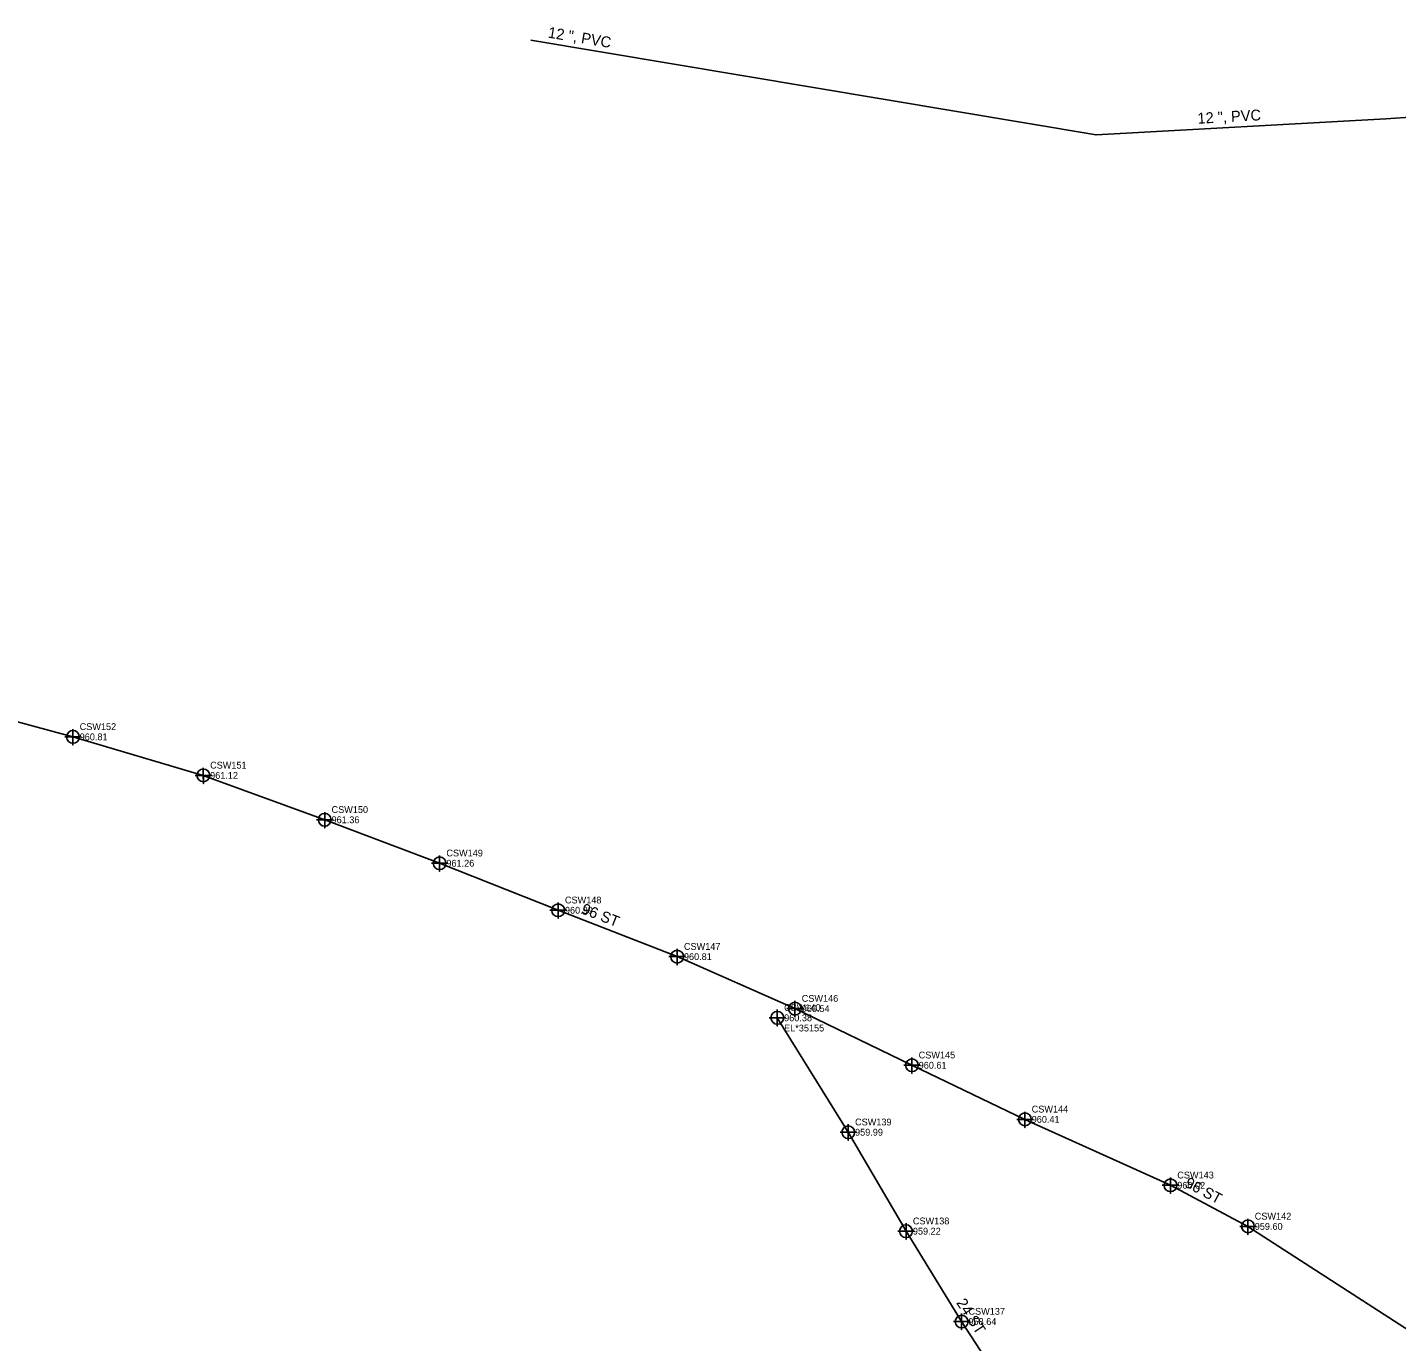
# Model space of a CAD drawing. Extents: x 1182504 to 1186036, y 573002 to 575111.
# Drawn here: x 1183491 to 1183993, y 573983 to 574465 of the extents above; entities that cross this region are included whole.
import ezdxf

# ---------------------------------------------------------------- set-up
doc = ezdxf.new("R2010")
doc.units = 0
for name, color, linetype in [('Exist Utilities Telephone UG Conduit SUE LOS B', 7, 'Continuous'), ('Exist Utilities Telephone UG Conduit SUE LOS B Cogo Elevation', 7, 'Continuous'), ('Exist Utilities Telephone UG Conduit SUE LOS B Cogo Number', 7, 'Continuous'), ('Exist Utilities Telephone UG Conduit SUE LOS B Cogo Point CELL', 7, 'Continuous'), ('Exist Utilities Telephone UG Conduit SUE LOS B Text', 7, 'Continuous'), ('Exist Utilities Telephone UG FO SUE LOS C', 7, 'Continuous'), ('Exist Utilities Telephone UG FO SUE LOS C Cogo Comment', 7, 'Continuous'), ('Exist Utilities Telephone UG FO SUE LOS C Cogo Elevation', 7, 'Continuous'), ('Exist Utilities Telephone UG FO SUE LOS C Cogo Number', 7, 'Continuous'), ('Exist Utilities Telephone UG FO SUE LOS C Cogo Point CELL', 7, 'Continuous'), ('Exist Utilities Telephone UG FO SUE LOS C Text', 7, 'Continuous'), ('Exist Utilities Water UG Line SUE LOS C', 7, 'Continuous'), ('Exist Utilities Water UG Line SUE LOS C Text', 7, 'Continuous')]:
    doc.layers.add(name, color=color, linetype=linetype)

msp = doc.modelspace()

# ---------------------------------------------------------------- linework, layer by layer
at = {"layer": 'Exist Utilities Telephone UG Conduit SUE LOS B'}
msp.add_lwpolyline([(1183461.9, 574217.61), (1183507.97, 574205.1), (1183555.78, 574190.97), (1183600.29, 574174.7), (1183642.38, 574158.78), (1183685.83, 574141.54), (1183729.44, 574124.53), (1183772.61, 574105.48), (1183815.48, 574084.72), (1183856.9, 574064.89), (1183910.26, 574040.72), (1183938.65, 574025.64), (1184017.13, 573974.93), (1184056.25, 573949.51), (1184095.95, 573918.75), (1184120.25, 573896.12), (1184153.18, 573876.37), (1184177.6, 573863.32)], dxfattribs=at)
at = {"layer": 'Exist Utilities Telephone UG Conduit SUE LOS B Cogo Point CELL'}
for points in [[(1183507.95, 574207.92), (1183507.99, 574202.1), (1183507.97, 574205.1), (1183510.99, 574205.1), (1183504.99, 574205.1)], [(1183555.76, 574193.78), (1183555.8, 574187.97), (1183555.78, 574190.97), (1183558.8, 574190.97), (1183552.8, 574190.97)], [(1183600.27, 574177.52), (1183600.3, 574171.7), (1183600.29, 574174.7), (1183603.3, 574174.7), (1183597.3, 574174.7)], [(1183642.36, 574161.59), (1183642.39, 574155.78), (1183642.38, 574158.78), (1183645.39, 574158.78), (1183639.39, 574158.78)], [(1183685.82, 574144.35), (1183685.85, 574138.54), (1183685.83, 574141.54), (1183688.85, 574141.54), (1183682.85, 574141.54)], [(1183729.43, 574127.34), (1183729.46, 574121.53), (1183729.44, 574124.53), (1183732.46, 574124.53), (1183726.46, 574124.53)], [(1183772.6, 574108.3), (1183772.63, 574102.48), (1183772.61, 574105.48), (1183775.63, 574105.48), (1183769.63, 574105.48)], [(1183815.46, 574087.53), (1183815.49, 574081.72), (1183815.48, 574084.72), (1183818.49, 574084.72), (1183812.49, 574084.72)], [(1183856.88, 574067.7), (1183856.91, 574061.89), (1183856.9, 574064.89), (1183859.91, 574064.89), (1183853.91, 574064.89)], [(1183910.25, 574043.54), (1183910.28, 574037.72), (1183910.26, 574040.72), (1183913.28, 574040.72), (1183907.28, 574040.72)], [(1183938.63, 574028.46), (1183938.66, 574022.64), (1183938.65, 574025.64), (1183941.66, 574025.64), (1183935.66, 574025.64)]]:
    msp.add_lwpolyline(points, dxfattribs=at)
for centre in [(1183507.99, 574205.1), (1183555.8, 574190.97), (1183600.3, 574174.7), (1183642.39, 574158.78), (1183685.85, 574141.54), (1183729.46, 574124.53), (1183772.63, 574105.48), (1183815.49, 574084.72), (1183856.91, 574064.89), (1183910.28, 574040.72), (1183938.66, 574025.64)]:
    msp.add_circle(centre, 2.34, dxfattribs=at)
at = {"layer": 'Exist Utilities Telephone UG FO SUE LOS C'}
msp.add_lwpolyline([(1183880.14, 573689.54), (1183880.21, 573736.69), (1183881.09, 573779.07), (1183880.73, 573825.31), (1183881.6, 573871.11), (1183878.51, 573913.09), (1183859.26, 573951.5), (1183833.73, 573990.76), (1183813.35, 574023.89), (1183792.16, 574060.17), (1183766.16, 574102.11)], dxfattribs=at)
at = {"layer": 'Exist Utilities Telephone UG FO SUE LOS C Cogo Point CELL'}
for points in [[(1183766.16, 574105.11), (1183766.16, 574099.11), (1183766.16, 574102.11), (1183769.16, 574102.11), (1183763.16, 574102.11)], [(1183792.16, 574063.17), (1183792.16, 574057.17), (1183792.16, 574060.17), (1183795.16, 574060.17), (1183789.16, 574060.17)], [(1183813.35, 574026.89), (1183813.35, 574020.89), (1183813.35, 574023.89), (1183816.35, 574023.89), (1183810.35, 574023.89)], [(1183833.73, 573993.76), (1183833.73, 573987.76), (1183833.73, 573990.76), (1183836.73, 573990.76), (1183830.73, 573990.76)]]:
    msp.add_lwpolyline(points, dxfattribs=at)
for centre in [(1183766.16, 574102.11), (1183792.16, 574060.17), (1183813.35, 574023.89), (1183833.73, 573990.76)]:
    msp.add_circle(centre, 2.34, dxfattribs=at)
at = {"layer": 'Exist Utilities Water UG Line SUE LOS C'}
msp.add_lwpolyline([(1183675.77, 574460.48), (1183882.99, 574425.76), (1183989.16, 574431.68), (1184300.95, 574453.14)], dxfattribs=at)

# ---------------------------------------------------------------- texts
at = {"layer": 'Exist Utilities Telephone UG Conduit SUE LOS B Cogo Elevation'}
for s, p in [('960.81', (1183510.47, 574203.85)), ('961.12', (1183558.28, 574189.72)), ('961.36', (1183602.79, 574173.45)), ('961.26', (1183644.88, 574157.53)), ('960.99', (1183688.33, 574140.29)), ('960.81', (1183731.94, 574123.28)), ('960.54', (1183775.11, 574104.23)), ('960.61', (1183817.98, 574083.47)), ('960.41', (1183859.4, 574063.64)), ('960.02', (1183912.76, 574039.47)), ('959.60', (1183941.15, 574024.39))]:
    msp.add_text(s, height=2.5, dxfattribs=at).set_placement(p)
at = {"layer": 'Exist Utilities Telephone UG Conduit SUE LOS B Cogo Number'}
for s, p in [('CSW152', (1183510.47, 574207.6)), ('CSW151', (1183558.28, 574193.47)), ('CSW150', (1183602.79, 574177.2)), ('CSW149', (1183644.88, 574161.28)), ('CSW148', (1183688.33, 574144.04)), ('CSW147', (1183731.94, 574127.03)), ('CSW146', (1183775.11, 574107.98)), ('CSW145', (1183817.98, 574087.22)), ('CSW144', (1183859.4, 574067.39)), ('CSW143', (1183912.76, 574043.22)), ('CSW142', (1183941.15, 574028.14))]:
    msp.add_text(s, height=2.5, dxfattribs=at).set_placement(p)
at = {"layer": 'Exist Utilities Telephone UG Conduit SUE LOS B Text'}
for rotation, p in [(338.6924, (1183694.02, 574140.49)), (332.0156, (1183915.17, 574040.38))]:
    msp.add_text('96 ST', height=4, rotation=rotation, dxfattribs=at).set_placement(p)
at = {"layer": 'Exist Utilities Telephone UG FO SUE LOS C Cogo Comment'}
msp.add_text('EL*35155', height=2.5, dxfattribs=at).set_placement((1183768.66, 574097.11))
at = {"layer": 'Exist Utilities Telephone UG FO SUE LOS C Cogo Elevation'}
for s, p in [('960.38', (1183768.66, 574100.86)), ('959.99', (1183794.66, 574058.92)), ('959.22', (1183815.85, 574022.64)), ('958.64', (1183836.23, 573989.51))]:
    msp.add_text(s, height=2.5, dxfattribs=at).set_placement(p)
at = {"layer": 'Exist Utilities Telephone UG FO SUE LOS C Cogo Number'}
for s, p in [('CSW140', (1183768.66, 574104.61)), ('CSW139', (1183794.66, 574062.67)), ('CSW138', (1183815.85, 574026.39)), ('CSW137', (1183836.23, 573993.26))]:
    msp.add_text(s, height=2.5, dxfattribs=at).set_placement(p)
at = {"layer": 'Exist Utilities Telephone UG FO SUE LOS C Text'}
msp.add_text('24 ST', height=4, rotation=303.037, dxfattribs=at).set_placement((1183831.63, 573997.65))
at = {"layer": 'Exist Utilities Water UG Line SUE LOS C Text'}
for rotation, p in [(350.4892, (1183681.92, 574461.47)), (3.1913, (1183920.27, 574429.84))]:
    msp.add_text('12 ", PVC', height=4, rotation=rotation, dxfattribs=at).set_placement(p)

doc.saveas('drawing.dxf')
